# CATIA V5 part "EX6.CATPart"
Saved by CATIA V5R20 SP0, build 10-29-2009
Part number: EX6
Bounding box of the stored display mesh (mm): x -76 to 52, y -116.681 to 100.143, z 0 to 10
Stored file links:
  E:\Nouveau dossier\tarek\mécaniquee\Catia\TP 0\EX6.CATPart
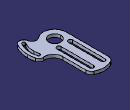
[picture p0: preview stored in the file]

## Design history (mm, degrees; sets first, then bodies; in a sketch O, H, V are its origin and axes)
Set1
  DatumSurface1 to DatumSurface29
Body1 (main body)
